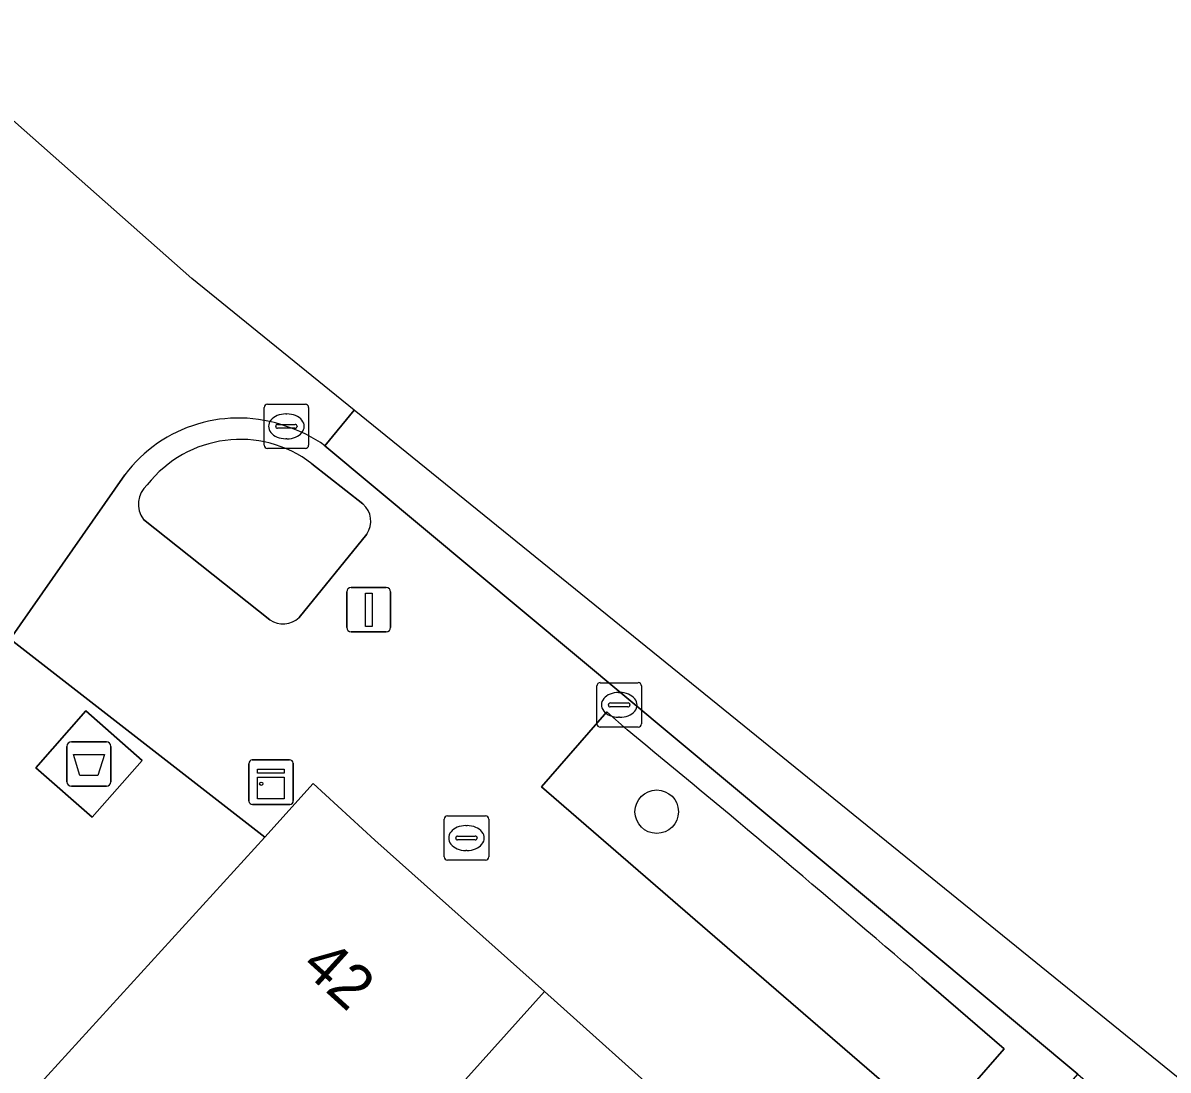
# Model space of a CAD drawing. Extents: x 161798 to 162385, y 382315 to 382833.
# Drawn here: x 161992.07 to 162017.86, y 382759.31 to 382782.9 of the extents above; entities that cross this region are included whole.
import ezdxf

# ---------------------------------------------------------------- set-up
doc = ezdxf.new("R2010")
doc.units = 0
for name, color, linetype in [('IMGEO_Afval_apart_plaats', 7, 'Continuous'), ('IMGEO_Boom', 7, 'Continuous'), ('IMGEO_Brandkraan', 7, 'Continuous'), ('IMGEO_Groenvoorziening', 7, 'Continuous'), ('IMGEO_Kast', 7, 'Continuous'), ('IMGEO_Kolk', 7, 'Continuous'), ('IMGEO_Lichtmast', 7, 'Continuous'), ('IMGEO_Pand', 7, 'Continuous'), ('IMGEO_Pand_nummerreeks', 7, 'Continuous'), ('IMGEO_Rijbaan_lokaal_gesloten', 7, 'Continuous'), ('IMGEO_Rijbaan_lokaal_open', 7, 'Continuous'), ('IMGEO_Voetpad_gesloten', 7, 'Continuous'), ('IMGEO_Voetpad_open', 7, 'Continuous')]:
    doc.layers.add(name, color=color, linetype=linetype)

msp = doc.modelspace()

# ---------------------------------------------------------------- linework, layer by layer
at = {"layer": 'IMGEO_Afval_apart_plaats'}
for p, q in [((161993.066, 382765.802), (161993.066, 382766.602)), ((161993.066, 382766.602), (161993.066, 382765.802)), ((161993.166, 382766.702), (161993.956, 382766.702)), ((161993.956, 382766.702), (161993.166, 382766.702)), ((161994.056, 382766.602), (161994.056, 382765.802)), ((161994.056, 382765.802), (161994.056, 382766.602)), ((161993.956, 382765.702), (161993.166, 382765.702)), ((161993.166, 382765.702), (161993.956, 382765.702))]:
    msp.add_line(p, q, dxfattribs=at)
msp.add_lwpolyline([(161993.209, 382766.416), (161993.913, 382766.416), (161993.764, 382765.946), (161993.358, 382765.946), (161993.209, 382766.416)], dxfattribs=at)
for centre, start, end in [((161993.166, 382766.602), 90, 180), ((161993.166, 382766.602), 90, 180), ((161993.956, 382766.602), 0, 90), ((161993.956, 382766.602), 360, 90), ((161993.166, 382765.802), 180, 270), ((161993.166, 382765.802), 180, 270), ((161993.956, 382765.802), 270, 0), ((161993.956, 382765.802), 270, 0)]:
    msp.add_arc(centre, 0.1, start, end, dxfattribs=at)
at = {"layer": 'IMGEO_Boom'}
msp.add_circle((162006.344, 382765.13), 0.489, dxfattribs=at)
at = {"layer": 'IMGEO_Brandkraan'}
for p, q in [((162001.635, 382765.036), (162002.487, 382765.036)), ((162001.56, 382764.11), (162001.56, 382764.962)), ((162002.048, 382764.816), (162002.073, 382764.816)), ((162002.561, 382764.962), (162002.561, 382764.11)), ((162001.819, 382764.53), (162001.819, 382764.542)), ((162001.862, 382764.579), (162002.26, 382764.579)), ((162002.303, 382764.542), (162002.303, 382764.53)), ((162002.257, 382764.493), (162001.859, 382764.493)), ((162002.071, 382764.256), (162002.046, 382764.256)), ((162002.487, 382764.036), (162001.635, 382764.036))]:
    msp.add_line(p, q, dxfattribs=at)
for points in [[(162001.635, 382765.036), (162002.487, 382765.036)], [(162001.56, 382764.11), (162001.56, 382764.962)], [(162002.561, 382764.962), (162002.561, 382764.11)], [(162002.487, 382764.036), (162001.635, 382764.036)]]:
    msp.add_lwpolyline(points, dxfattribs=at)
for centre, radius, start, end in [((162001.637, 382764.96), 0.0765, 91.552, 178.448), ((162001.637, 382764.96), 0.0765, 91.552, 178.448), ((162002.485, 382764.96), 0.0765, 1.552, 88.448), ((162002.485, 382764.96), 0.0765, 1.552, 88.448), ((162001.859, 382764.539), 0.0403, 85.8775, 175.7526), ((162001.856, 382764.529), 0.0366, 178.938, 274.7102), ((162002.26, 382764.536), 0.043, 264.8664, 352.4533), ((162002.264, 382764.541), 0.0386, 1.7309, 96.639), ((162001.637, 382764.112), 0.0765, 181.552, 268.448), ((162001.637, 382764.112), 0.0765, 181.552, 268.448), ((162002.485, 382764.112), 0.0765, 271.552, 358.448), ((162002.485, 382764.112), 0.0765, 271.552, 358.448)]:
    msp.add_arc(centre, radius, start, end, dxfattribs=at)
for centre, major_axis, ratio, start_param, end_param in [((162002.047, 382764.536), (-0.387, 0.002), 0.722429, 4.712389, 7.853982), ((162002.072, 382764.536), (-0.39, 0.002), 0.717154, 1.570796, 4.712389)]:
    msp.add_ellipse(centre, major_axis=major_axis, ratio=ratio, start_param=start_param, end_param=end_param, dxfattribs=at)
at = {"layer": 'IMGEO_Groenvoorziening'}
for points in [[(161999.729, 382772.062), (161998.58, 382772.968)], [(161994.789, 382771.712), (161997.634, 382769.452)], [(161998.292, 382769.505), (161999.818, 382771.384)], [(162005.677, 382766.977), (162005.224, 382767.376), (162003.748, 382765.691), (162007.491, 382762.457), (162012.625, 382758.014), (162014.168, 382759.79)], [(162014.168, 382759.79), (162012.313, 382761.387)]]:
    msp.add_lwpolyline(points, dxfattribs=at)
for centre, radius, start, end in [((161996.967, 382770.869), 2.647, 52.4571, 142.2152), ((161995.234, 382772.057), 0.563, 129.6211, 217.7792), ((161999.39, 382771.673), 0.516, 325.9844, 48.9723), ((161997.93, 382769.884), 0.524, 235.5243, 313.6859), ((161758.796, 382467.165), 388.378, 49.25002, 50.53008)]:
    msp.add_arc(centre, radius, start, end, dxfattribs=at)
at = {"layer": 'IMGEO_Kast'}
for p, q in [((161997.162, 382765.37), (161997.162, 382766.211)), ((161997.162, 382766.211), (161997.162, 382765.37)), ((161997.237, 382766.295), (161998.078, 382766.295)), ((161998.078, 382766.295), (161997.237, 382766.295)), ((161998.162, 382766.22), (161998.162, 382765.379)), ((161998.162, 382765.379), (161998.162, 382766.22)), ((161998.087, 382765.295), (161997.246, 382765.295)), ((161997.246, 382765.295), (161998.087, 382765.295))]:
    msp.add_line(p, q, dxfattribs=at)
for points in [[(161997.357, 382766.085), (161997.957, 382766.085), (161997.957, 382766), (161997.357, 382766), (161997.357, 382766.085)], [(161997.357, 382765.91), (161997.957, 382765.91), (161997.957, 382765.421), (161997.357, 382765.421), (161997.357, 382765.91)]]:
    msp.add_lwpolyline(points, dxfattribs=at)
msp.add_circle((161997.441, 382765.759), 0.0377, dxfattribs=at)
for centre, start, end in [((161997.24, 382766.217), 92.4484, 184.2845), ((161997.24, 382766.217), 92.4484, 184.2845), ((161998.084, 382766.217), 2.4484, 94.2845), ((161998.084, 382766.217), 2.4484, 94.2845), ((161997.24, 382765.373), 182.4484, 274.2845), ((161997.24, 382765.373), 182.4484, 274.2845), ((161998.084, 382765.373), 272.4484, 4.2845), ((161998.084, 382765.373), 272.4484, 4.2845)]:
    msp.add_arc(centre, 0.0779, start, end, dxfattribs=at)
at = {"layer": 'IMGEO_Kolk'}
for p, q in [((161997.581, 382774.31), (161998.433, 382774.31)), ((161997.506, 382773.384), (161997.506, 382774.236)), ((161997.994, 382774.09), (161998.019, 382774.09)), ((161998.507, 382774.236), (161998.507, 382773.384)), ((161997.765, 382773.804), (161997.765, 382773.816)), ((161997.808, 382773.853), (161998.206, 382773.853)), ((161998.249, 382773.816), (161998.249, 382773.804)), ((161998.203, 382773.767), (161997.805, 382773.767)), ((161998.017, 382773.53), (161997.992, 382773.53)), ((161998.433, 382773.31), (161997.581, 382773.31)), ((162004.999, 382767.11), (162004.999, 382767.962)), ((162005.074, 382768.036), (162005.926, 382768.036)), ((162006, 382767.962), (162006, 382767.11)), ((162005.487, 382767.816), (162005.512, 382767.816)), ((162005.258, 382767.53), (162005.258, 382767.542)), ((162005.696, 382767.493), (162005.298, 382767.493)), ((162005.301, 382767.579), (162005.699, 382767.579)), ((162005.742, 382767.542), (162005.742, 382767.53)), ((162005.51, 382767.256), (162005.485, 382767.256)), ((162005.926, 382767.036), (162005.074, 382767.036))]:
    msp.add_line(p, q, dxfattribs=at)
for points in [[(161997.581, 382774.31), (161998.433, 382774.31)], [(161997.506, 382773.384), (161997.506, 382774.236)], [(161998.507, 382774.236), (161998.507, 382773.384)], [(161998.433, 382773.31), (161997.581, 382773.31)], [(162004.999, 382767.11), (162004.999, 382767.962)], [(162005.074, 382768.036), (162005.926, 382768.036)], [(162006, 382767.962), (162006, 382767.11)], [(162005.926, 382767.036), (162005.074, 382767.036)]]:
    msp.add_lwpolyline(points, dxfattribs=at)
for centre, radius, start, end in [((161997.583, 382774.234), 0.0765, 91.552, 178.448), ((161997.583, 382774.234), 0.0765, 91.552, 178.448), ((161998.431, 382774.234), 0.0765, 1.552, 88.448), ((161998.431, 382774.234), 0.0765, 1.552, 88.448), ((161997.805, 382773.813), 0.0403, 85.8775, 175.7526), ((161997.802, 382773.803), 0.0366, 178.938, 274.7102), ((161998.206, 382773.81), 0.043, 264.8664, 352.4533), ((161998.21, 382773.815), 0.0386, 1.7309, 96.639), ((161997.583, 382773.386), 0.0765, 181.552, 268.448), ((161997.583, 382773.386), 0.0765, 181.552, 268.448), ((161998.431, 382773.386), 0.0765, 271.552, 358.448), ((161998.431, 382773.386), 0.0765, 271.552, 358.448), ((162005.076, 382767.96), 0.0765, 91.552, 178.448), ((162005.076, 382767.96), 0.0765, 91.552, 178.448), ((162005.924, 382767.96), 0.0765, 1.552, 88.448), ((162005.924, 382767.96), 0.0765, 1.552, 88.448), ((162005.298, 382767.539), 0.0403, 85.8775, 175.7526), ((162005.295, 382767.529), 0.0366, 178.938, 274.7102), ((162005.699, 382767.536), 0.043, 264.8664, 352.4533), ((162005.703, 382767.541), 0.0386, 1.7309, 96.639), ((162005.076, 382767.112), 0.0765, 181.552, 268.448), ((162005.076, 382767.112), 0.0765, 181.552, 268.448), ((162005.924, 382767.112), 0.0765, 271.552, 358.448), ((162005.924, 382767.112), 0.0765, 271.552, 358.448)]:
    msp.add_arc(centre, radius, start, end, dxfattribs=at)
for centre, major_axis, ratio, start_param, end_param in [((161997.993, 382773.81), (-0.387, 0.002), 0.722429, 4.712389, 7.853982), ((161998.018, 382773.81), (-0.39, 0.002), 0.717154, 1.570796, 4.712389), ((162005.486, 382767.536), (-0.387, 0.002), 0.722429, 4.712389, 7.853982), ((162005.511, 382767.536), (-0.39, 0.002), 0.717154, 1.570796, 4.712389)]:
    msp.add_ellipse(centre, major_axis=major_axis, ratio=ratio, start_param=start_param, end_param=end_param, dxfattribs=at)
at = {"layer": 'IMGEO_Lichtmast'}
for p, q in [((161999.464, 382770.179), (162000.254, 382770.179)), ((162000.254, 382770.179), (161999.464, 382770.179)), ((161999.364, 382769.279), (161999.364, 382770.079)), ((161999.364, 382770.079), (161999.364, 382769.279)), ((162000.354, 382770.079), (162000.354, 382769.279)), ((162000.354, 382769.279), (162000.354, 382770.079)), ((162000.254, 382769.179), (161999.464, 382769.179)), ((161999.464, 382769.179), (162000.254, 382769.179))]:
    msp.add_line(p, q, dxfattribs=at)
msp.add_lwpolyline([(161999.784, 382770.054), (161999.934, 382770.054), (161999.934, 382769.304), (161999.784, 382769.304), (161999.784, 382770.054)], dxfattribs=at)
for centre, start, end in [((161999.464, 382770.079), 90, 180), ((161999.464, 382770.079), 90, 180), ((162000.254, 382770.079), 0, 90), ((162000.254, 382770.079), 360, 90), ((161999.464, 382769.279), 180, 270), ((161999.464, 382769.279), 180, 270), ((162000.254, 382769.279), 270, 0), ((162000.254, 382769.279), 270, 0)]:
    msp.add_arc(centre, 0.1, start, end, dxfattribs=at)
at = {"layer": 'IMGEO_Pand'}
for points in [[(162000, 382756.824), (162003.821, 382761.079), (162000, 382764.491), (161998.609, 382765.767), (161997.519, 382764.558), (161984.249, 382750), (161981.747, 382747.198), (161985.478, 382743.87), (161987.064, 382742.454), (161991.557, 382747.445), (161991.488, 382747.507), (161993.712, 382750), (161995.75, 382752.284), (161995.84, 382752.203)], [(162009.776, 382755.729), (162003.821, 382761.079), (162000, 382756.824), (161995.84, 382752.203), (161998.309, 382750), (162000, 382748.49), (162001.581, 382747.078), (162004.62, 382750)]]:
    msp.add_lwpolyline(points, close=True, dxfattribs=at)
at = {"layer": 'IMGEO_Rijbaan_lokaal_gesloten'}
msp.add_lwpolyline([(162024.654, 382753.809), (161999.533, 382774.178), (161998.874, 382773.374), (162015.823, 382759.219), (162017.838, 382757.467), (162031.597, 382745.168), (162033.775, 382743.194), (162033.82, 382743.154), (162036.171, 382741.054), (162043.452, 382734.52), (162045.887, 382732.315), (162046.684, 382731.604), (162048.13, 382730.285), (162049.418, 382731.719), (162037.507, 382742.354)], close=True, dxfattribs=at)
at = {"layer": 'IMGEO_Rijbaan_lokaal_open'}
for points in [[(161999.533, 382774.178), (161995.879, 382777.141), (161989.366, 382782.899), (161988.419, 382781.669)], [(161998.874, 382773.374), (161999.533, 382774.178)], [(161989.611, 382773.497), (161988.335, 382771.671), (161991.783, 382769.02), (161994.37, 382772.717)]]:
    msp.add_lwpolyline(points, dxfattribs=at)
for centre, radius, start, end in [((161996.928, 382770.802), 3.196, 70.2759, 143.1775), ((161997.114, 382770.954), 2.992, 53.9701, 72.6357)]:
    msp.add_arc(centre, radius, start, end, dxfattribs=at)
at = {"layer": 'IMGEO_Voetpad_gesloten'}
msp.add_lwpolyline([(161994.758, 382766.286), (161993.49, 382767.4), (161992.364, 382766.119), (161993.632, 382765.005)], close=True, dxfattribs=at)
at = {"layer": 'IMGEO_Voetpad_open'}
for points in [[(162016.94, 382755.601), (162016.605, 382755.616), (162014.402, 382757.569), (162015.823, 382759.219), (161998.874, 382773.374)], [(161998.58, 382772.968), (161999.729, 382772.062)], [(161994.37, 382772.717), (161991.783, 382769.02), (161991.848, 382768.97), (161997.519, 382764.558), (161998.609, 382765.767), (162000, 382764.491), (162003.821, 382761.079), (162009.776, 382755.729), (162015.335, 382750.798), (162016.083, 382750.117), (162017.324, 382748.986), (162022.858, 382743.945), (162027.754, 382739.543), (162038.012, 382730.344), (162043.809, 382725.145), (162045.819, 382722.219)], [(161997.634, 382769.452), (161994.789, 382771.712)], [(161999.818, 382771.384), (161998.292, 382769.505)], [(161953.212, 382706.879), (161955.826, 382710.123), (161981.747, 382747.198), (161984.249, 382750), (161997.519, 382764.558), (161991.848, 382768.97), (161991.783, 382769.02)], [(162012.625, 382758.014), (162007.491, 382762.457), (162003.748, 382765.691), (162005.224, 382767.376), (162005.677, 382766.977)], [(162012.313, 382761.387), (162014.168, 382759.79), (162012.625, 382758.014)]]:
    msp.add_lwpolyline(points, dxfattribs=at)
msp.add_lwpolyline([(161992.364, 382766.119), (161993.49, 382767.4), (161994.758, 382766.286), (161993.632, 382765.005)], close=True, dxfattribs=at)
for centre, radius, start, end in [((161996.928, 382770.802), 3.196, 70.2759, 143.1775), ((161997.114, 382770.954), 2.992, 53.9701, 72.6357), ((161996.967, 382770.869), 2.647, 52.4571, 142.2152), ((161995.234, 382772.057), 0.563, 129.6211, 217.7792), ((161999.39, 382771.673), 0.516, 325.9844, 48.9723), ((161997.93, 382769.884), 0.524, 235.5243, 313.6859), ((161758.796, 382467.165), 388.378, 49.25002, 50.53008)]:
    msp.add_arc(centre, radius, start, end, dxfattribs=at)

# ---------------------------------------------------------------- texts
at = {"layer": 'IMGEO_Pand_nummerreeks'}
msp.add_text('42', height=1, rotation=317.8017, dxfattribs=at).set_placement((161998.306, 382761.599))

doc.saveas('drawing.dxf')
